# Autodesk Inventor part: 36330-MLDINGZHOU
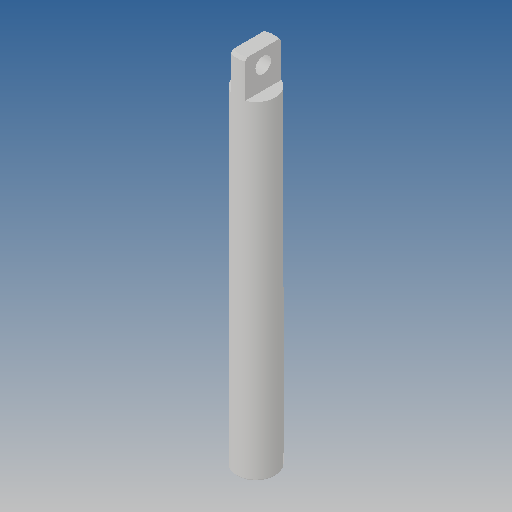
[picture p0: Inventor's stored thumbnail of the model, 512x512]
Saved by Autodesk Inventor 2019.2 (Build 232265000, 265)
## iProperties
Created: 2012-06
Part Number: 36330-MLDINGZHOU
Material: Ogólny
Document SubType Name: Modeling
Designer: CADENGINEERING4
Density: 1 g/cm^3
Appearance: Domyślna
Author: CADENGINEERING4
Revision Number: 2LAST_VERSION
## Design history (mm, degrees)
feature "Baza1"
node "Bryła1"
